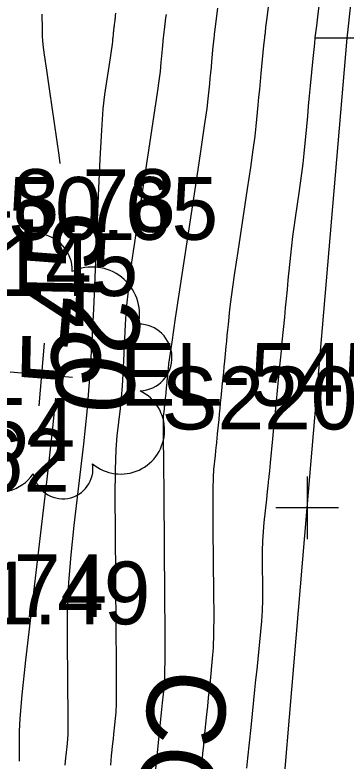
# Model space of a CAD drawing. Extents: x 1724534 to 1727318, y 657156 to 660047.
# Drawn here: x 1725510.28 to 1725531.4, y 659024.97 to 659072.53 of the extents above; entities that cross this region are included whole.
import ezdxf

# ---------------------------------------------------------------- set-up
doc = ezdxf.new("R2010")
doc.units = 0
for name, color, linetype in [('SURVEY - CONTOURS - Index with Text', 7, 'Continuous'), ('SURVEY - CONTOURS - Intermediate with optional Text', 7, 'Continuous'), ('SURVEY - DTM - Breaklines', 7, 'Continuous'), ('SURVEY - DTM - Breaklines - Points - Locators', 7, 'Continuous'), ('SURVEY - DTM - Breaklines - Points - Numbers', 7, 'Continuous'), ('SURVEY - NON-TRANSPORTATION - Features Text', 7, 'Continuous'), ('SURVEY - ROADSIDE BARRIERS - Points - Elevations', 7, 'Continuous'), ('SURVEY - TRANSPORTATION - Features - Points - Elevations', 7, 'Continuous'), ('SURVEY - TRANSPORTATION - Roads - Points - Elevations', 7, 'Continuous'), ('SURVEY - VEGETATION - Features - Points - Elevations', 7, 'Continuous'), ('SURVEY - VEGETATION - Features - Points - Locators', 7, 'Continuous'), ('SURVEY - VEGETATION - Features - Points - Numbers', 7, 'Continuous'), ('SURVEY - VEGETATION - Features with Text', 7, 'Continuous')]:
    doc.layers.add(name, color=color, linetype=linetype)

msp = doc.modelspace()

# ---------------------------------------------------------------- linework, layer by layer
at = {"layer": 'SURVEY - CONTOURS - Index with Text'}
for points in [[(1725529.79, 659074.158), (1725529.578, 659072.412), (1725529.508, 659071.839), (1725529.417, 659071.089), (1725529.415, 659071.07), (1725529.383, 659070.733), (1725529.343, 659070.323), (1725529.288, 659069.752), (1725529.12, 659068.014), (1725529.057, 659067.363), (1725528.994, 659066.714), (1725528.931, 659066.065), (1725528.869, 659065.417), (1725528.702, 659063.692), (1725528.635, 659063.051), (1725528.562, 659062.421), (1725528.482, 659061.803), (1725528.394, 659061.196), (1725528.151, 659059.594), (1725528.063, 659058.993), (1725527.985, 659058.395), (1725527.914, 659057.799), (1725527.852, 659057.204), (1725527.697, 659055.621), (1725527.639, 659055.029), (1725527.581, 659054.438), (1725527.523, 659053.848), (1725527.465, 659053.261), (1725527.312, 659051.696), (1725527.255, 659051.11), (1725527.198, 659050.526), (1725527.141, 659049.943), (1725526.875, 659047.236), (1725526.819, 659046.658), (1725526.706, 659045.508), (1725526.556, 659043.978), (1725526.507, 659043.476), (1725526.472, 659043.115), (1725526.45, 659042.896), (1725526.443, 659042.819), (1725526.441, 659042.803), (1725526.433, 659042.727), (1725526.41, 659042.513), (1725526.372, 659042.16), (1725526.32, 659041.668), (1725526.161, 659040.171), (1725526.109, 659039.596), (1725526.074, 659038.992), (1725526.056, 659038.36), (1725526.054, 659037.699), (1725526.071, 659035.899), (1725526.068, 659035.226), (1725526.047, 659034.557), (1725526.007, 659033.892), (1725525.949, 659033.23), (1725525.769, 659031.472), (1725525.702, 659030.814), (1725525.634, 659030.157), (1725525.567, 659029.501), (1725525.5, 659028.848), (1725525.322, 659027.107), (1725525.123, 659025.156), (1725525.056, 659024.509)], [(1725511.997, 659072.568), (1725512.003, 659072.264), (1725512.005, 659072.151), (1725512.008, 659072.04), (1725512.01, 659071.932), (1725512.012, 659071.827), (1725512.018, 659071.55), (1725512.02, 659071.447), (1725512.022, 659071.346), (1725512.024, 659071.247), (1725512.026, 659071.151), (1725512.032, 659070.896), (1725512.061, 659070.622), (1725512.146, 659069.991), (1725512.286, 659069.003), (1725512.482, 659067.658), (1725513.077, 659063.595), (1725513.142, 659063.062)], [(1725512.859, 659048.092), (1725512.651, 659045.99), (1725512.31, 659042.942), (1725511.296, 659034.288), (1725510.964, 659031.391), (1725510.728, 659029.192), (1725510.588, 659027.69), (1725510.544, 659026.886), (1725510.556, 659025.67), (1725510.559, 659025.264), (1725510.559, 659024.958)]]:
    msp.add_lwpolyline(points, dxfattribs=at)
at = {"layer": 'SURVEY - CONTOURS - Intermediate with optional Text'}
for points in [[(1725526.491, 659073.554), (1725526.326, 659072.199), (1725526.272, 659071.754), (1725526.233, 659071.435), (1725526.21, 659071.241), (1725526.202, 659071.172), (1725526.2, 659071.158), (1725526.193, 659071.089), (1725526.175, 659070.896), (1725526.144, 659070.578), (1725526.101, 659070.135), (1725525.971, 659068.787), (1725525.922, 659068.282), (1725525.873, 659067.778), (1725525.824, 659067.275), (1725525.776, 659066.773), (1725525.646, 659065.434), (1725525.575, 659064.808), (1725525.46, 659063.934), (1725525.3, 659062.811), (1725525.095, 659061.439), (1725524.489, 659057.451), (1725524.286, 659056.098), (1725524.131, 659055.03), (1725524.024, 659054.247), (1725523.965, 659053.749), (1725523.873, 659052.802), (1725523.838, 659052.447), (1725523.803, 659052.093), (1725523.769, 659051.741), (1725523.734, 659051.389), (1725523.643, 659050.453), (1725523.608, 659050.102), (1725523.574, 659049.753), (1725523.54, 659049.404), (1725523.506, 659049.056), (1725523.415, 659048.131), (1725523.381, 659047.784), (1725523.347, 659047.438), (1725523.314, 659047.094), (1725523.28, 659046.75), (1725523.19, 659045.835), (1725523.161, 659045.534), (1725523.14, 659045.318), (1725523.127, 659045.187), (1725523.122, 659045.141), (1725523.121, 659045.131), (1725523.116, 659045.086), (1725523.103, 659044.958), (1725523.08, 659044.747), (1725523.049, 659044.452), (1725522.953, 659043.557), (1725522.924, 659043.07), (1725522.907, 659042.281), (1725522.903, 659041.19), (1725522.911, 659039.797), (1725522.951, 659035.679), (1725522.957, 659034.261), (1725522.945, 659033.093), (1725522.916, 659032.178), (1725522.87, 659031.513), (1725522.723, 659030.076), (1725522.667, 659029.537), (1725522.612, 659029), (1725522.558, 659028.464), (1725522.503, 659027.93), (1725522.357, 659026.507), (1725522.303, 659025.974), (1725522.248, 659025.442), (1725522.194, 659024.912)], [(1725523.191, 659072.949), (1725523.008, 659071.443), (1725522.991, 659071.305), (1725522.985, 659071.245), (1725522.98, 659071.197), (1725522.967, 659071.06), (1725522.945, 659070.834), (1725522.914, 659070.519), (1725522.822, 659069.56), (1725522.787, 659069.201), (1725522.752, 659068.843), (1725522.718, 659068.485), (1725522.683, 659068.128), (1725522.591, 659067.176), (1725522.515, 659066.565), (1725522.358, 659065.446), (1725522.118, 659063.818), (1725521.796, 659061.682), (1725520.509, 659053.202), (1725520.278, 659051.664), (1725520.135, 659050.695), (1725520.079, 659050.294), (1725520.049, 659049.982), (1725520.037, 659049.866), (1725520.026, 659049.749), (1725520.014, 659049.633), (1725520.003, 659049.518), (1725519.973, 659049.21), (1725519.962, 659049.094), (1725519.928, 659048.75), (1725519.898, 659048.446), (1725519.876, 659048.218), (1725519.865, 659048.105), (1725519.854, 659047.992), (1725519.824, 659047.691), (1725519.815, 659047.592), (1725519.808, 659047.521), (1725519.803, 659047.478), (1725519.802, 659047.463), (1725519.802, 659047.46), (1725519.8, 659047.445), (1725519.795, 659047.403), (1725519.746, 659046.942), (1725519.739, 659046.543), (1725519.74, 659045.569), (1725519.75, 659044.02), (1725519.769, 659041.894), (1725519.83, 659035.459), (1725519.845, 659033.295), (1725519.843, 659031.63), (1725519.825, 659030.464), (1725519.79, 659029.796), (1725519.676, 659028.679), (1725519.633, 659028.261), (1725519.591, 659027.844), (1725519.548, 659027.428), (1725519.35, 659025.493), (1725519.308, 659025.08), (1725519.223, 659024.257)], [(1725516.703, 659072.648), (1725516.681, 659072.465), (1725516.672, 659072.397), (1725516.664, 659072.329), (1725516.656, 659072.26), (1725516.647, 659072.192), (1725516.625, 659072.011), (1725516.617, 659071.943), (1725516.601, 659071.808), (1725516.592, 659071.74), (1725516.571, 659071.56), (1725516.558, 659071.458), (1725516.554, 659071.423), (1725516.554, 659071.421), (1725516.553, 659071.412), (1725516.55, 659071.387), (1725516.546, 659071.344), (1725516.541, 659071.286), (1725516.523, 659071.106), (1725516.517, 659071.039), (1725516.51, 659070.972), (1725516.497, 659070.838), (1725516.48, 659070.661), (1725516.462, 659070.52), (1725516.42, 659070.23), (1725516.355, 659069.792), (1725515.999, 659067.445), (1725515.898, 659066.548), (1725515.797, 659065.177), (1725515.694, 659063.334), (1725515.59, 659061.017), (1725515.312, 659054.208), (1725515.193, 659051.73), (1725515.042, 659049.402), (1725514.86, 659047.224), (1725514.646, 659045.196), (1725514.036, 659039.99), (1725513.838, 659038.106), (1725513.7, 659036.359), (1725513.623, 659034.749), (1725513.606, 659033.275), (1725513.641, 659029.527), (1725513.651, 659028.276), (1725513.652, 659027.331), (1725513.646, 659026.692), (1725513.632, 659026.361), (1725513.583, 659025.886), (1725513.547, 659025.531), (1725513.529, 659025.354), (1725513.511, 659025.177), (1725513.462, 659024.707)], [(1725519.918, 659072.559), (1725519.892, 659072.345), (1725519.822, 659071.773), (1725519.8, 659071.585), (1725519.783, 659071.45), (1725519.773, 659071.369), (1725519.77, 659071.34), (1725519.766, 659071.305), (1725519.759, 659071.223), (1725519.746, 659071.089), (1725519.672, 659070.333), (1725519.652, 659070.12), (1725519.631, 659069.908), (1725519.611, 659069.695), (1725519.59, 659069.483), (1725519.536, 659068.918), (1725519.478, 659068.471), (1725519.346, 659067.553), (1725519.139, 659066.163), (1725518.858, 659064.302), (1725518.009, 659058.712), (1725517.726, 659056.77), (1725517.514, 659055.136), (1725517.372, 659053.811), (1725517.302, 659052.794), (1725517.208, 659050.494), (1725517.168, 659049.657), (1725517.117, 659048.871), (1725517.055, 659048.136), (1725516.983, 659047.451), (1725516.777, 659045.692), (1725516.712, 659044.821), (1725516.672, 659043.526), (1725516.657, 659041.807), (1725516.667, 659039.664), (1725516.727, 659033.385), (1725516.743, 659031.287), (1725516.746, 659029.703), (1725516.735, 659028.634), (1725516.711, 659028.078), (1725516.63, 659027.282), (1725516.569, 659026.687), (1725516.538, 659026.391), (1725516.508, 659026.095), (1725516.427, 659025.307), (1725516.397, 659025.012), (1725516.367, 659024.718)]]:
    msp.add_lwpolyline(points, dxfattribs=at)
at = {"layer": 'SURVEY - DTM - Breaklines'}
msp.add_lwpolyline([(1725525.942, 659009.271), (1725526.399, 659011.158), (1725528.918, 659041.105), (1725531.461, 659071.052), (1725534.8, 659101.37), (1725536.346, 659131.334), (1725539.898, 659161.171), (1725544.971, 659191.09), (1725550.75, 659220.691), (1725554.674, 659250.537), (1725558.308, 659280.317), (1725560.346, 659299.038), (1725563.922, 659328.825), (1725567.992, 659357.481)], dxfattribs=at)
at = {"layer": 'SURVEY - DTM - Breaklines - Points - Locators'}
for p, q in [((1725533.461, 659071.052), (1725529.461, 659071.052)), ((1725528.918, 659043.105), (1725528.918, 659039.105)), ((1725530.918, 659041.105), (1725526.918, 659041.105))]:
    msp.add_line(p, q, dxfattribs=at)
at = {"layer": 'SURVEY - VEGETATION - Features - Points - Locators'}
for p, q in [((1725512.139, 659051.605), (1725511.801, 659047.619)), ((1725509.977, 659049.781), (1725513.963, 659049.443))]:
    msp.add_line(p, q, dxfattribs=at)
at = {"layer": 'SURVEY - VEGETATION - Features with Text'}
msp.add_circle((1725511.93, 659049.747), 0.0978, dxfattribs=at)
for centre, radius, start, end in [((1725511.599, 659056.249), 2.34, 358.2631, 173.2634), ((1725515.211, 659053.443), 3.016, 348.1042, 114.9499), ((1725518.168, 659050.692), 2.129, 272.8171, 90.1363), ((1725517.029, 659046.06), 2.798, 230.1985, 63.6182), ((1725509.151, 659044.886), 2.804, 168.0616, 324.8506), ((1725513.337, 659043.612), 1.924, 190.1778, 8.9234)]:
    msp.add_arc(centre, radius, start, end, dxfattribs=at)

# ---------------------------------------------------------------- texts
at = {"layer": 'SURVEY - CONTOURS - Index with Text'}
msp.add_text('545', height=5, rotation=88.9191, dxfattribs=at).set_placement((1725515.694, 659048.8))
at = {"layer": 'SURVEY - DTM - Breaklines - Points - Numbers'}
msp.add_text('S2203', height=4, dxfattribs=at).set_placement((1725519.63, 659046.105))
at = {"layer": 'SURVEY - NON-TRANSPORTATION - Features Text'}
msp.add_text('CONC', height=5, rotation=263.195, dxfattribs=at).set_placement((1725519.022, 659031.016))
at = {"layer": 'SURVEY - ROADSIDE BARRIERS - Points - Elevations'}
for s, p in [('EL-550.65', (1725498.561, 659058.194)), ('EL-551.49', (1725494.239, 659033.685))]:
    msp.add_text(s, height=4, dxfattribs=at).set_placement(p)
at = {"layer": 'SURVEY - TRANSPORTATION - Features - Points - Elevations'}
for s, p in [('EL-548.78', (1725495.855, 659058.693)), ('EL-549.74', (1725491.478, 659034.153))]:
    msp.add_text(s, height=4, dxfattribs=at).set_placement(p)
at = {"layer": 'SURVEY - TRANSPORTATION - Roads - Points - Elevations'}
for s, p in [('EL-549.54', (1725489.442, 659044.101)), ('EL-549.62', (1725489.106, 659042.131))]:
    msp.add_text(s, height=4, dxfattribs=at).set_placement(p)
at = {"layer": 'SURVEY - VEGETATION - Features - Points - Elevations'}
msp.add_text('EL-545.54', height=4, dxfattribs=at).set_placement((1725516.97, 659047.612))
at = {"layer": 'SURVEY - VEGETATION - Features - Points - Numbers'}
msp.add_text('S2145', height=4, dxfattribs=at).set_placement((1725502.682, 659054.612))
at = {"layer": 'SURVEY - VEGETATION - Features with Text'}
msp.add_text('20', height=5, rotation=265.1461, dxfattribs=at).set_placement((1725513.389, 659054.792))

doc.saveas('drawing.dxf')
